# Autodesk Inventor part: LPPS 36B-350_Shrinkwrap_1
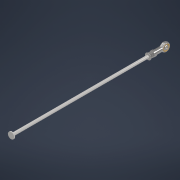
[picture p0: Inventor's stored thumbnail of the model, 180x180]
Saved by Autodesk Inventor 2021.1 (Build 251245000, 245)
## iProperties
Created: 2020-09
Part Number: LPPS 36B-350_Shrinkwrap_1
Material: Generic
Document SubType Name: Modeling
Designer: J. Nielson
Density: 1 g/cm^3
Appearance: Default
Author: J. Nielson
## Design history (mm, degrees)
derived "LPPS 36B-350.iam"
body "Solid1"
node "LPPS-36B-350 ROD.ipt:1"
node "Custom Flanged Nut.ipt:1"
body "Solid2"
node "FEMALE Rod End SW.ipt:1"
body "Solid3"
node "JIS B 1181 - M8x1(4).ipt:1"
body "Solid4"
